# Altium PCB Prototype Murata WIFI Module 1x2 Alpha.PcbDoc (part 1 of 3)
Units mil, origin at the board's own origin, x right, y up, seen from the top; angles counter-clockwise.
Board outline 708.66 x 1594.49 mil, 6 copper layers (Component Side, Ground Plane (GND), Inner Layer 1, Inner Layer 2, Power Plane (VCC), Solder Side), stack 20.279 mil thick; 197 components, 116 nets, 943 pads, 479 vias.
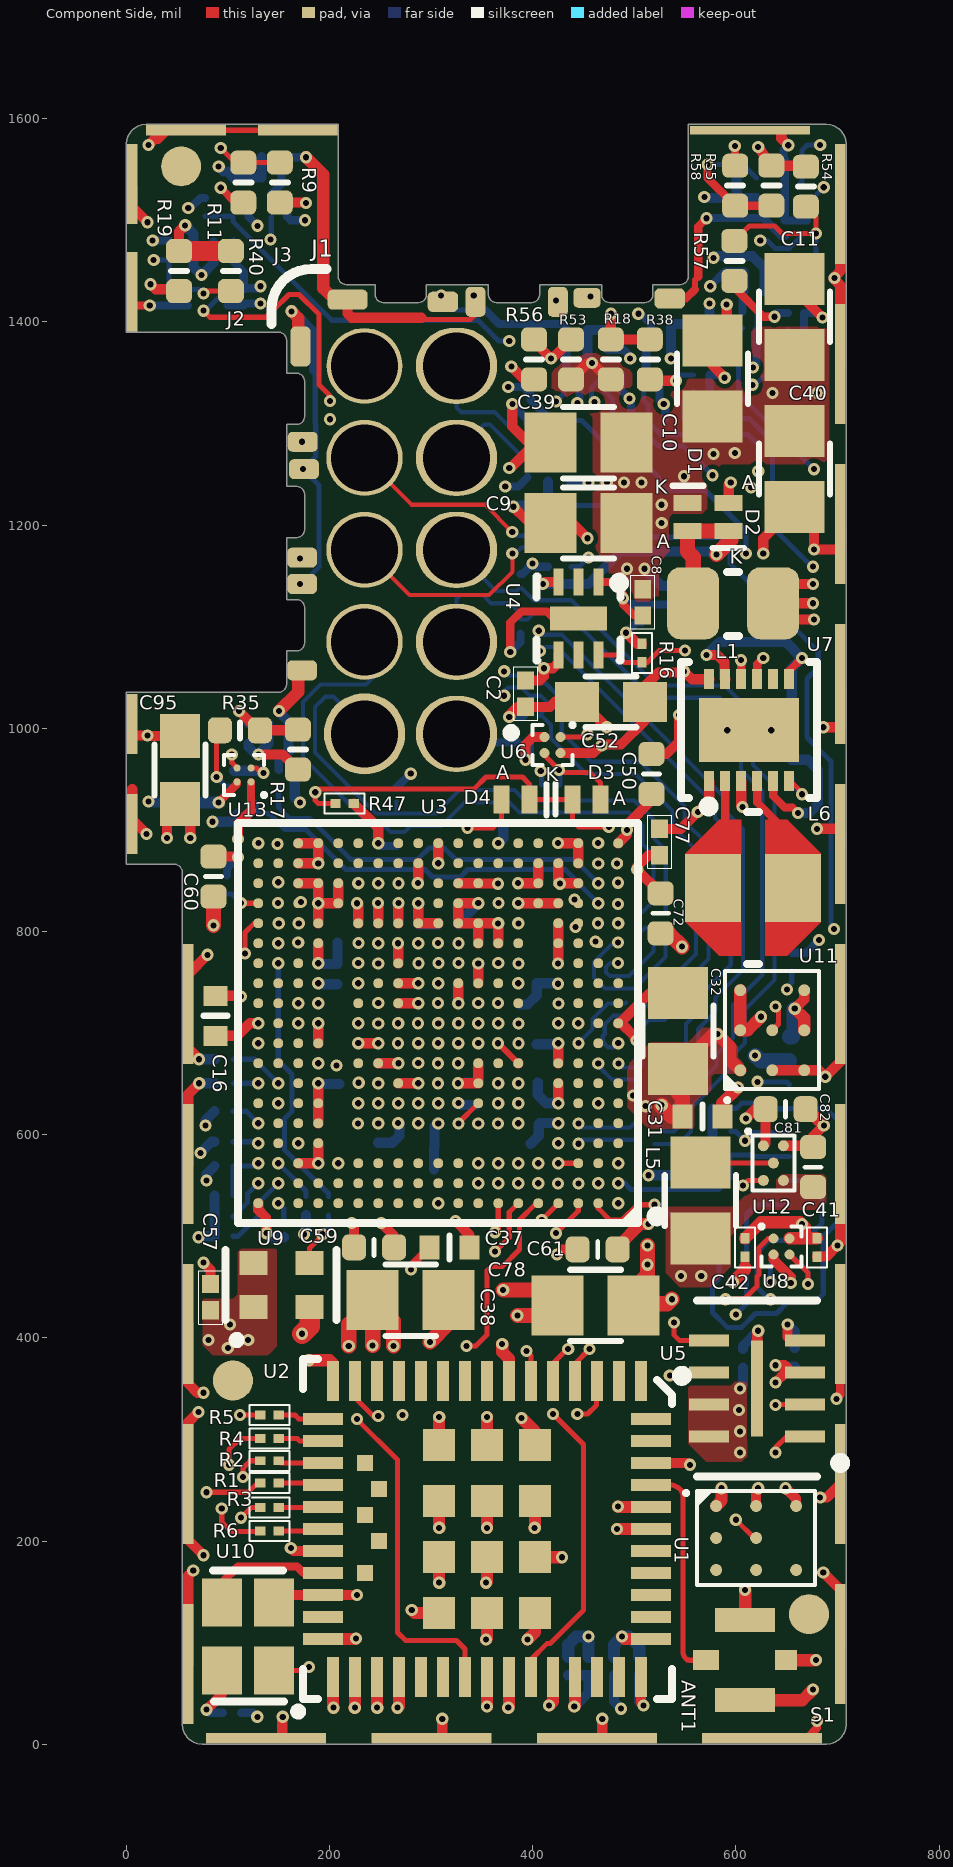
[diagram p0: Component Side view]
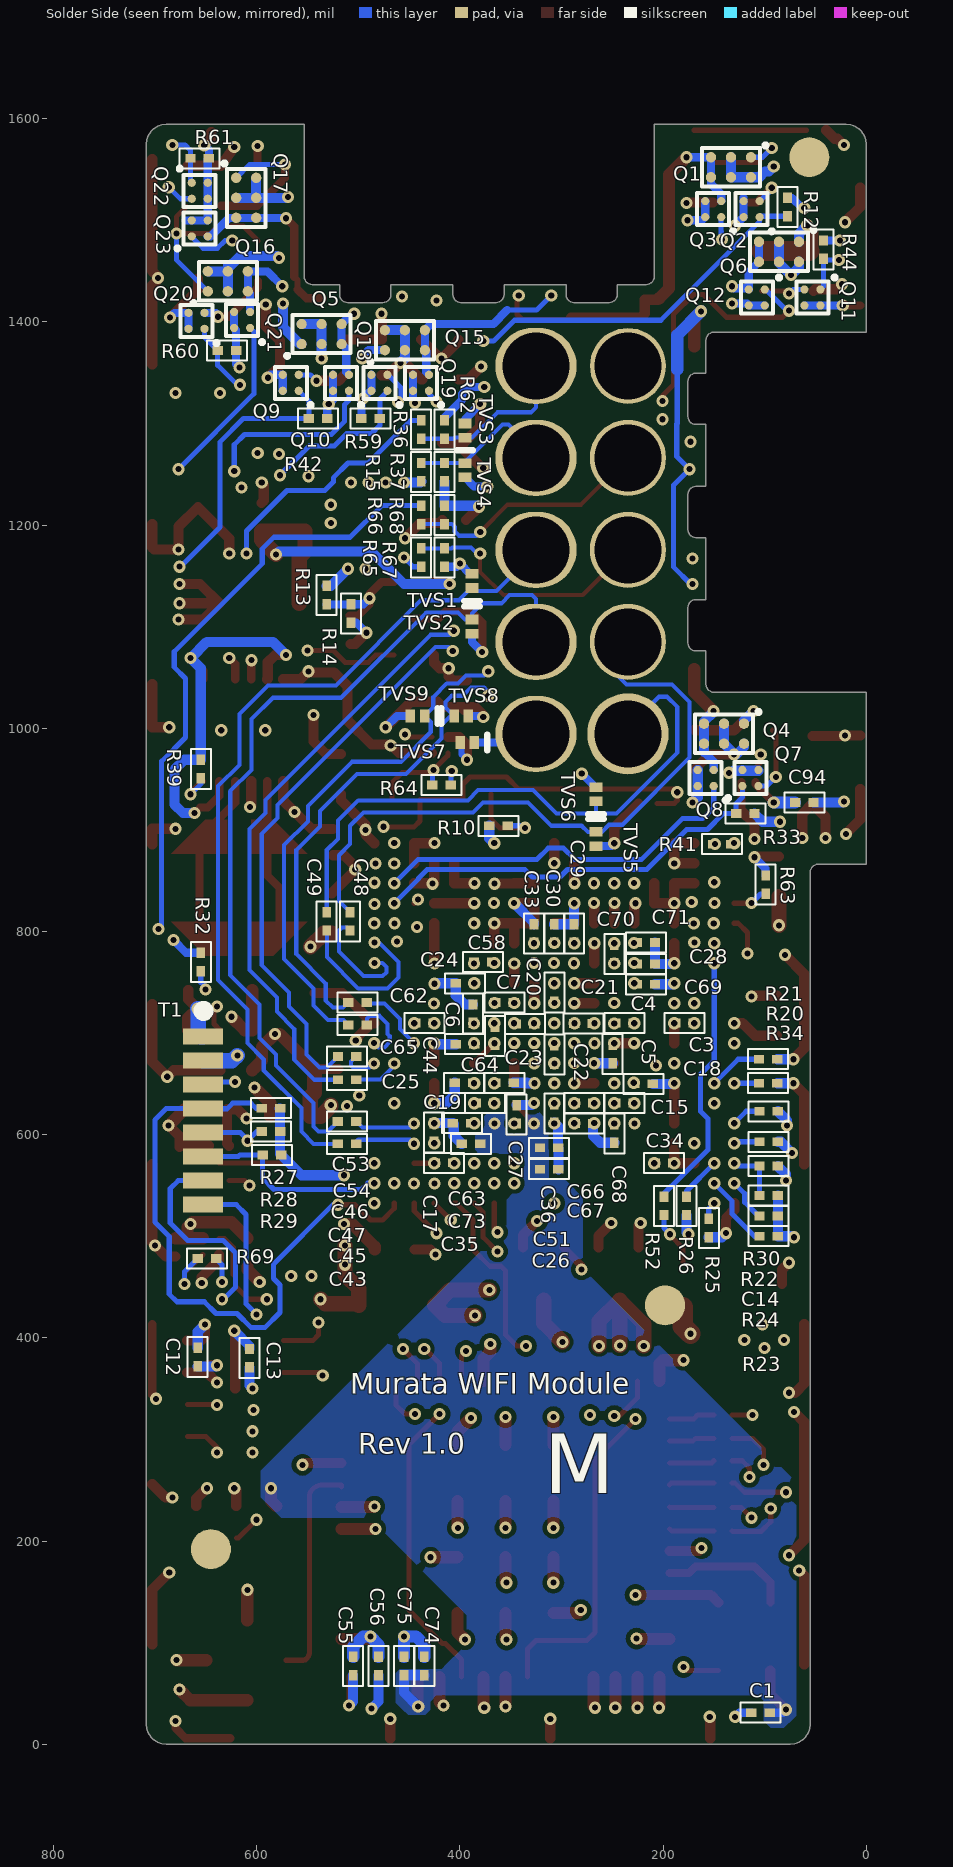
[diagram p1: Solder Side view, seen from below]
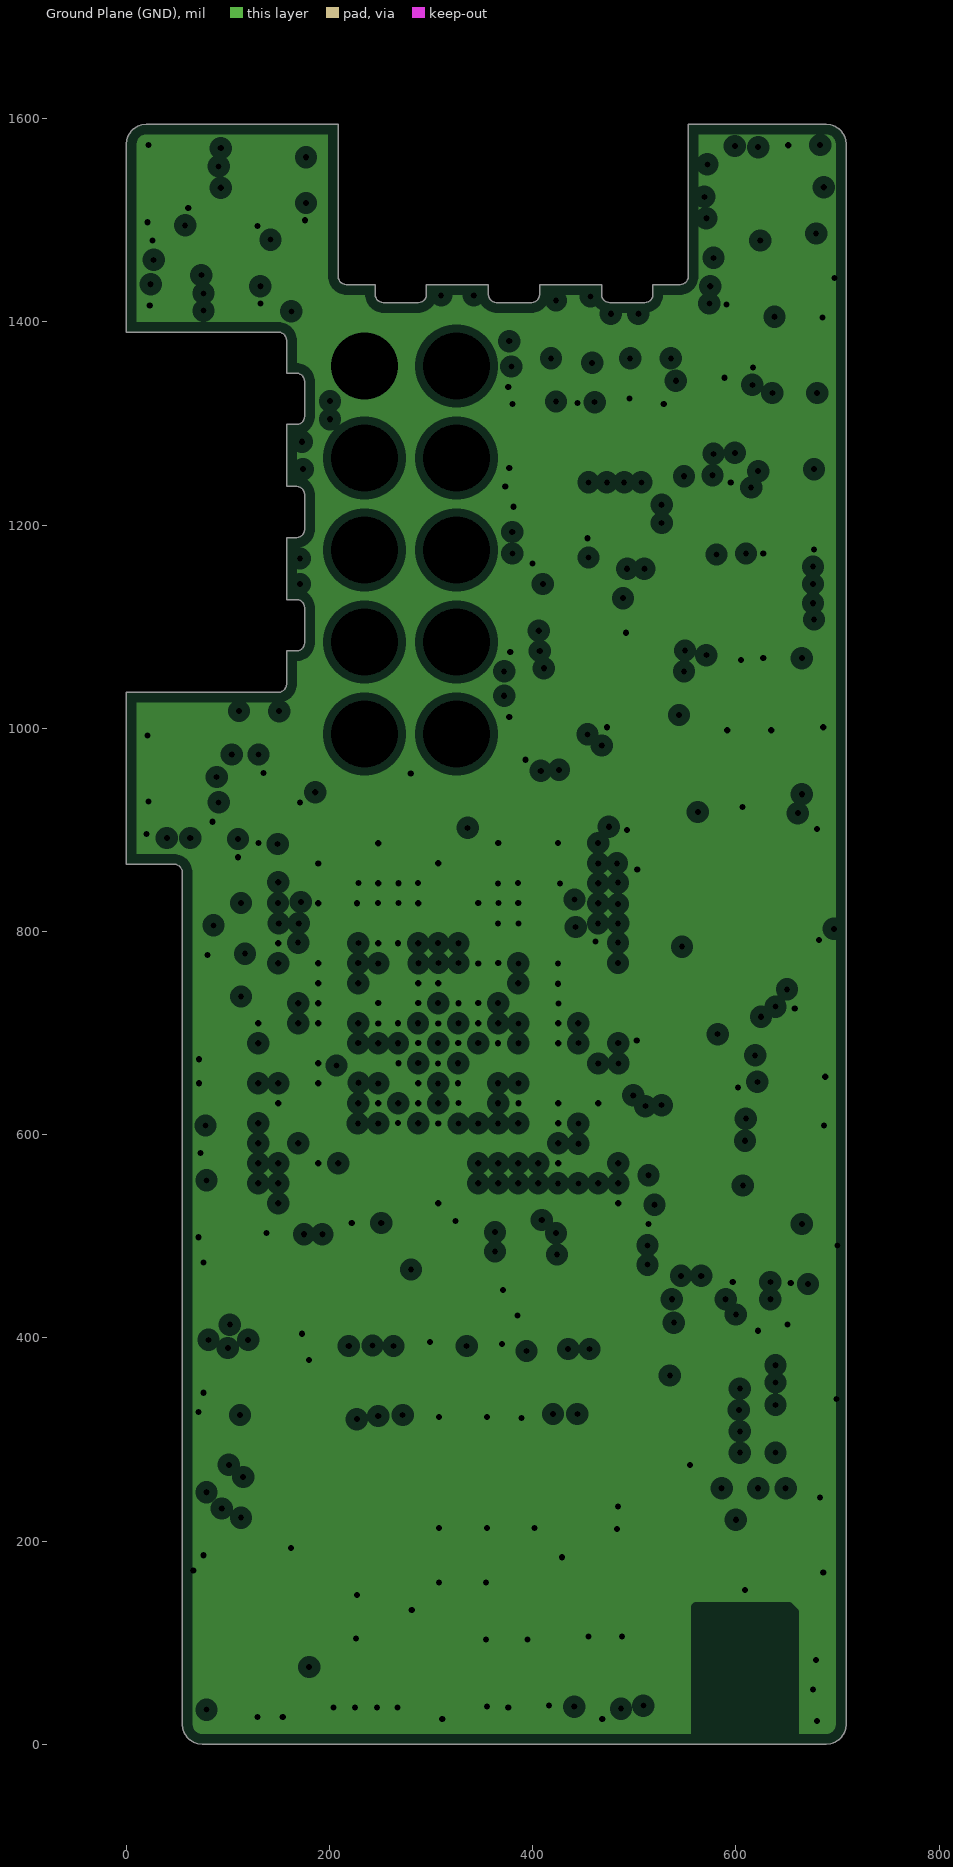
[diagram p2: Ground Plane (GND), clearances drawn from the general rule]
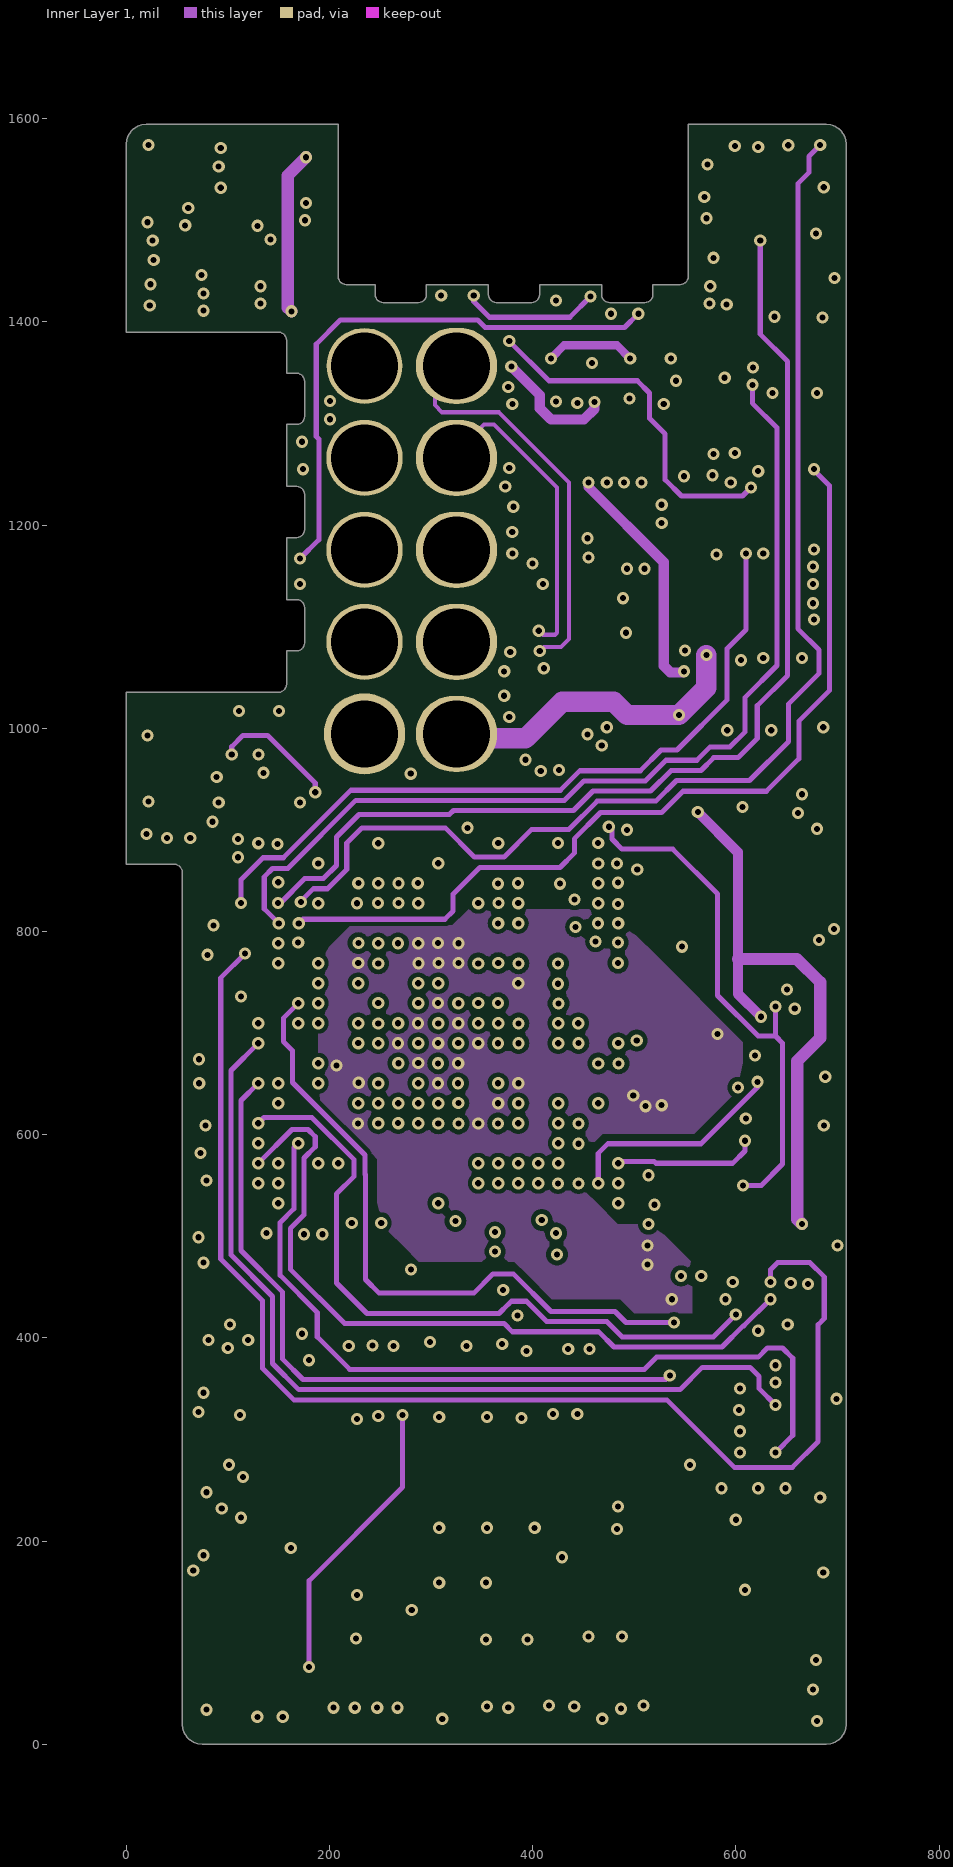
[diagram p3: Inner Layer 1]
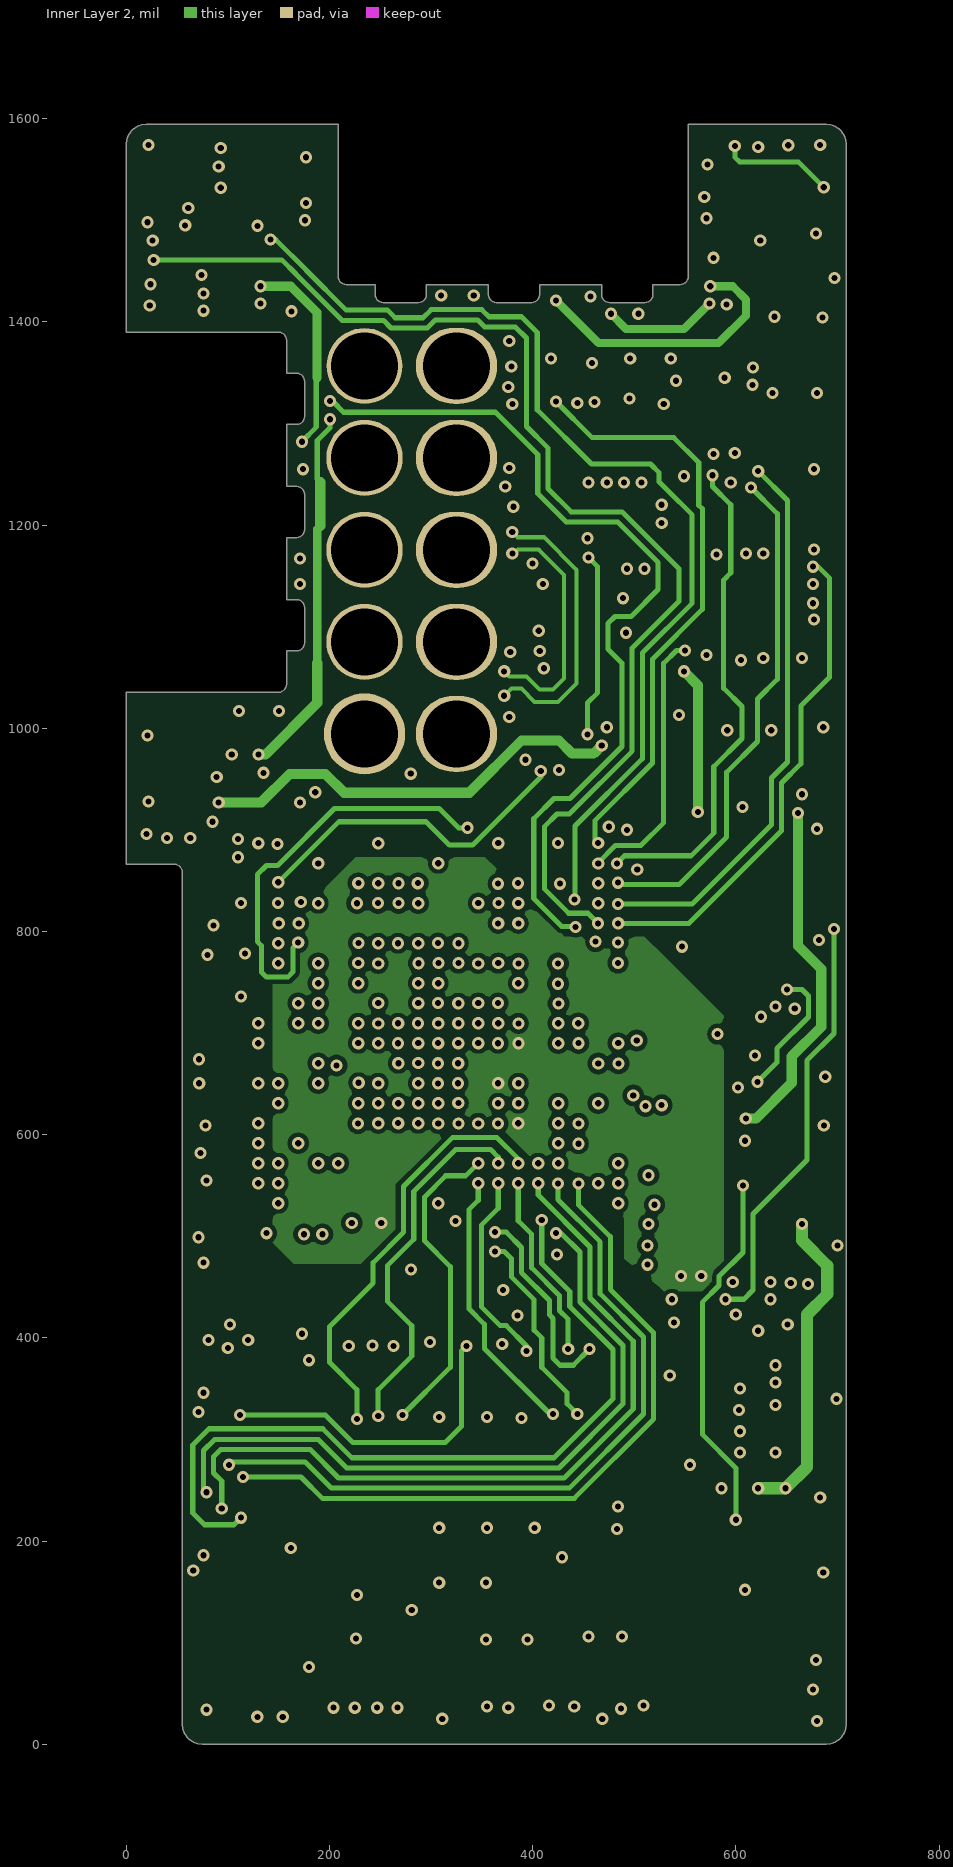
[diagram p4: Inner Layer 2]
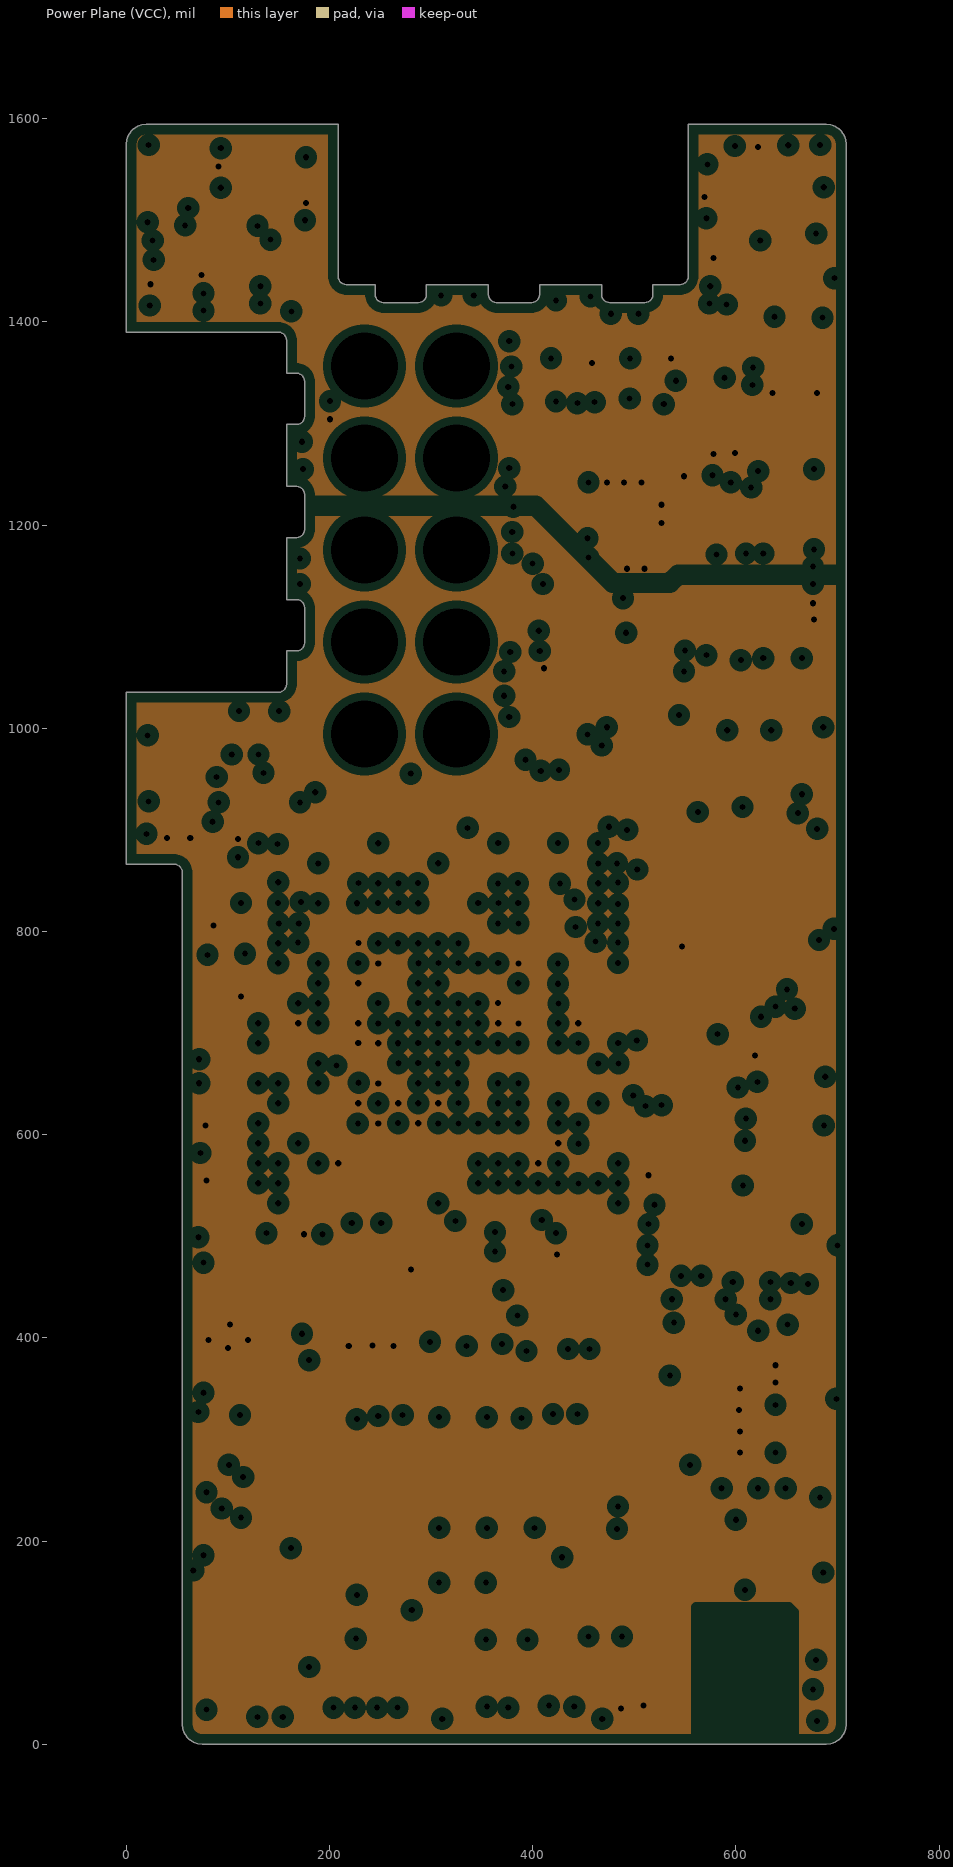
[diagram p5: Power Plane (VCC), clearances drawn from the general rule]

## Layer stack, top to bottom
Component Side: signal copper 1.4
Dielectric: core 1.9685, FR-4, Dk 4.8
Ground Plane (GND): plane copper 1.4169, net GND
Dielectric: prepreg 1.9685, Dk 4.2
Inner Layer 1: signal copper 1.4169
Dielectric: core 3.937, Dk 4.2
Inner Layer 2: signal copper 1.4169
Dielectric: prepreg 1.9685, Dk 4.2
Power Plane (VCC): plane copper 1.4169, net (Multiple Nets)
Dielectric: core 1.9685, Dk 4.2
Solder Side: signal copper 1.4

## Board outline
157.87,1076.18 157.87,1043.31 157.68,1041.55 157.09,1039.89 156.16,1038.4 154.91,1037.15 153.42,1036.21 151.75,1035.63 150,1035.43 0,1035.43 0,866.14 47.24,866.14 49,865.94 50.66,865.36 52.15,864.42 53.4,863.18 54.34,861.68 54.92,860.02 55.12,858.27 55.12,19.68 55.61,15.3 57.07,11.14 59.41,7.41 62.53,4.29 66.26,1.95 70.42,0.49 74.8,0 688.98,0 693.36,0.49 697.52,1.95 701.25,4.29 704.37,7.41 706.71,11.14 708.17,15.3 708.66,19.68 708.66,1574.8 708.17,1579.18 706.71,1583.34 704.37,1587.08 701.25,1590.19 697.52,1592.54 693.36,1593.99 688.98,1594.49 553.15,1594.49 553.15,1444.49 552.95,1442.74 552.37,1441.07 551.43,1439.58 550.18,1438.33 548.69,1437.39 547.03,1436.81 545.28,1436.61 518.31,1436.61 518.31,1426.77 518.11,1425.02 517.53,1423.36 516.59,1421.86 515.34,1420.62 513.85,1419.68 512.19,1419.09 510.43,1418.9 475.79,1418.9 474.04,1419.09 472.37,1419.68 470.88,1420.62 469.63,1421.86 468.69,1423.36 468.11,1425.02 467.91,1426.77 467.91,1436.61 406.89,1436.61 406.89,1426.77 406.69,1425.02 406.11,1423.36 405.17,1421.86 403.93,1420.62 402.43,1419.68 400.77,1419.09 399.02,1418.9 364.37,1418.9 362.62,1419.09 360.95,1419.68 359.46,1420.62 358.21,1421.86 357.28,1423.36 356.69,1425.02 356.5,1426.77 356.5,1436.61 295.47,1436.61 295.47,1426.77 295.27,1425.02 294.69,1423.36 293.75,1421.86 292.51,1420.62 291.01,1419.68 289.35,1419.09 287.6,1418.9 252.95,1418.9 251.2,1419.09 249.54,1419.68 248.04,1420.62 246.8,1421.86 245.86,1423.36 245.28,1425.02 245.08,1426.77 245.08,1436.61 216.54,1436.61 214.78,1436.81 213.12,1437.39 211.63,1438.33 210.38,1439.58 209.44,1441.07 208.86,1442.74 208.66,1444.49 208.66,1594.49 19.68,1594.49 15.3,1593.99 11.14,1592.54 7.41,1590.19 4.29,1587.08 1.95,1583.34 0.49,1579.18 0,1574.8 0,1389.76 150,1389.76 151.75,1389.57 153.42,1388.98 154.91,1388.05 156.16,1386.8 157.09,1385.31 157.68,1383.64 157.87,1381.89 157.87,1349.41 167.72,1349.41 169.47,1349.21 171.13,1348.63 172.63,1347.69 173.87,1346.44 174.81,1344.95 175.39,1343.29 175.59,1341.54 175.59,1306.89 175.39,1305.14 174.81,1303.47 173.87,1301.98 172.63,1300.73 171.13,1299.8 169.47,1299.21 167.72,1299.02 157.87,1299.02 157.87,1237.99 167.72,1237.99 169.47,1237.79 171.13,1237.21 172.63,1236.27 173.87,1235.03 174.81,1233.53 175.39,1231.87 175.59,1230.12 175.59,1195.47 175.39,1193.72 174.81,1192.06 173.87,1190.56 172.63,1189.32 171.13,1188.38 169.47,1187.8 167.72,1187.6 157.87,1187.6 157.87,1126.57 167.72,1126.57 169.47,1126.38 171.13,1125.79 172.63,1124.86 173.87,1123.61 174.81,1122.12 175.39,1120.45 175.59,1118.7 175.59,1084.05 175.39,1082.3 174.81,1080.64 173.87,1079.15 172.63,1077.9 171.13,1076.96 169.47,1076.38 167.72,1076.18

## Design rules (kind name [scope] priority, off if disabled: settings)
Clearance diff_1 [InNetClass('diff')] p1: gap=5
Clearance [All] p2: gap=4.5
DiffPairsRouting [All] p1: maxlimit=8 minlimit=8 mostfreqgap=8 maxuncoupledlength=500
FabricationTestPointUsage [All] p1 off: valid=0 allowmultiple=FALSE
FabricationTestpoint [(IsPad And (OnTopLayer Or OnBottomLayer))] p1 off: side=3 testpointundercomponent=TRUE minsize=40 maxsize=100 preferedsize=60 minholesize=0 maxholesize=40 preferedholesize=32 testpointgrid=1 allowsidetop=TRUE allowsidebottom=TRUE usegrid=TRUE gridtolerance=0.01
MatchedLengths DiffPair_MatchedLengths [InDifferentialPair ('SERDES_TX_CHIP')] p1: tolerance=1000 checknetsindiffpair=TRUE checkdiffpairvsdiffpair=TRUE checkothers=TRUE
MatchedLengths DiffPair_MatchedLengths_1 [InDifferentialPair ('SERDES_TX')] p2: tolerance=1000 checknetsindiffpair=TRUE checkdiffpairvsdiffpair=TRUE checkothers=TRUE
MatchedLengths DiffPair_MatchedLengths_2 [InDifferentialPair ('SERDES_RX')] p3: tolerance=1000 checknetsindiffpair=TRUE checkdiffpairvsdiffpair=TRUE checkothers=TRUE
MatchedLengths DiffPair_MatchedLengths_3 [InDifferentialPair ('RCLK_100MHZ')] p4: tolerance=1000 checknetsindiffpair=TRUE checkdiffpairvsdiffpair=TRUE checkothers=TRUE
MatchedLengths DiffPair_MatchedLengths_4 [InDifferentialPair ('OSC_100MHZ')] p5: tolerance=1000 checknetsindiffpair=TRUE checkdiffpairvsdiffpair=TRUE checkothers=TRUE
MinimumSolderMaskSliver [All] p1: minsoldermaskwidth=3
PlaneClearance [All] p1: clearance=8
PlaneConnect [All] p1: planeconnectstyle=Direct reliefexpansion=8 reliefentries=4 reliefconductorwidth=8 reliefairgap=8
PolygonConnect [All] p1: connectstyle=Direct reliefconductorwidth=10 reliefentries=4 polygonreliefangle="90 Angle"
RoutingVias [All] p1: holewidth=6 width=12 viastyle="Through Hole" minholewidth=6 minwidth=12 maxholewidth=6 maxwidth=12
SilkToSilkClearance [All] p1: silktosilkclearance=3
SilkscreenOverComponentPads SilkToSolderMaskClearance [IsPad] p1: minsilkscreentomaskgap=3
SolderMaskExpansion [All] p1: expansion=4
Width diff [InNetClass('diff')] p1: maxlimit=4 minlimit=4 preferedwidth=4
Width [All] p2: maxlimit=30 minlimit=4 preferedwidth=5
20 further rules are at their usual default settings.

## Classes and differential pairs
differential pair TX: +TX_P -TX_N
differential pair TX_CLK: +TX_CLK_P -TX_CLK_N
differential pair RX: +RX_P -RX_N
differential pair RX_CLK: +RX_CLK_P -RX_CLK_N
differential pair C_TX: +C_TX_P -C_TX_N
differential pair C_TX_CLK: +C_TX_CLK_P -C_TX_CLK_N
differential pair C_RX: +C_RX_P -C_RX_N
differential pair C_RX_CLK: +C_RX_CLK_P -C_RX_CLK_N

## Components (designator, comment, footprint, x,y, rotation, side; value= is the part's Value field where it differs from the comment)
ANT1 "Ultra Miniature Coaxial" W.FL2-R-SMT-1 609.25,82.68 r270 top locked
C1 "0.1uF" C_01005#1 104,31 r180 bottom
C2 "0.1uF" CAPC0201 393,1034 r90 top
C3 "0.1uF" C_01005#2 179,710 r180 bottom
C4 "0.1uF" C_01005#2 238,710 r180 bottom
C5 "0.1uF" C_01005#2 249.51,679.24 r90 bottom
C6 "0.1uF" C_01005#2 387,719 r270 bottom
C7 "0.1uF" C_01005#2 356,730 r0 bottom
C8 "C_0201_22pF" CAPC0201 508.42,1124 r90 top
C9 "22µF" C_ERA-0805 454.79,1202 r0 top
C10 "22µF" C_ERA-0805 577,1344 r270 top
C11 "22µF" C_ERA-0805 657.7,1405 r270 top
C12 "0.1uF" C_01005#2 658,381 r90 bottom
C13 "0.1uF" C_01005#2 607,380 r90 bottom
C14 "0.1uF" C_01005#2 96,540 r180 bottom
C15 "0.1uF" C_01005#2 238,631 r0 bottom
C16 "1.0uF" C_ERA-0402 88,717 r90 top
C17 "0.1uF" C_01005#2 425.51,602.24 r90 bottom
C18 "0.1uF" C_01005#2 219,650 r0 bottom
C19 "0.1uF" C_01005#2 375,631 r180 bottom
C20 "0.1uF" C_01005#2 307,740 r270 bottom
C21 "0.1uF" C_01005#2 278.51,709.24 r0 bottom
C22 "0.1uF" C_01005#2 307,679 r90 bottom
C23 "0.1uF" C_01005#2 336,709 r180 bottom
C24 "0.1uF" C_01005#2 395,749 r180 bottom
C25 "0.1uF" C_01005#2 396,651 r180 bottom
C26 "0.1uF" C_01005#2 312,566 r0 bottom
C27 "0.1uF" C_01005#2 344,620 r270 bottom
C28 "0.1uF" C_01005#2 217,768 r0 bottom
C29 "0.1uF" C_01005#2 287.5,798 r270 bottom
C30 "0.1uF" C_01005#2 307,798 r270 bottom
C31 "1.0uF" C_ERA-0402 567,618 r180 top
C32 "22uF" C_ERA-0805 543,702 r270 top
C33 "0.1uF" C_01005#2 327,798 r270 bottom
C34 "0.1uF" C_01005#2 199,572 r0 bottom
C35 "0.1uF" C_01005#2 415.51,572.24 r180 bottom
C36 "0.1uF" C_01005#2 307,621 r90 bottom
C37 "1.0uF" C_ERA-0402 318,489 r180 top
C38 "22uF" C_ERA-0805 280,437 r180 top
C39 "22µF" C_ERA-0805 454.87,1281 r0 top
C40 "22µF" C_ERA-0805 657.8,1255 r90 top
C41 "0.1UF" C_01005#1 680,489 r90 top
C42 "0.1uF" C_01005#1 609,489 r90 top
C43 "0.1uF" C_01005#2 511.04,591 r180 bottom
C44 "0.1uF" C_01005#2 365.51,697.24 r90 bottom
C45 "0.1uF" C_01005#2 510.95,613 r180 bottom
C46 "0.1uF" C_01005#2 510.85,677 r180 bottom
C47 "0.1uF" C_01005#2 510.85,654 r180 bottom
C48 "0.1uF" C_01005#2 508.06,810 r270 bottom
C49 "0.1uF" C_01005#2 531,810 r270 bottom
C50 "10uF" C_0402 517,955 r90 top
C51 "0.1uF" C_01005#2 312,587 r0 bottom
C52 "22uF" C_ERA-0603 477,1026 r0 top
C53 "0.1uF" C_01005#2 500.73,730 r180 bottom
C54 "0.1uF" C_01005#2 500.59,708 r180 bottom
C55 "0.1uF" C_01005#1 505,77 r270 bottom
C56 "0.1uF" C_01005#1 480,77 r270 bottom
C57 "0.47µF" CAPC0201 83,440 r270 top
C58 "0.1uF" C_01005#2 377,770 r0 bottom
C59 "10uF" C_0402 244,489 r0 top
C60 "10uF" C_0402 85.91,854 r270 top
C61 "10uF" C_0402 464,487 r180 top
C62 "0.1uF" C_01005#2 435,710 r0 bottom
C63 "0.1uF" C_01005#2 398,611.3 r180 bottom
C64 "0.1uF" C_01005#2 356,651 r0 bottom
C65 "0.1uF" C_01005#2 395,689 r180 bottom
C66 "0.1uF" C_01005#2 278,631 r180 bottom
C67 "0.1uF" C_01005#2 278,611 r0 bottom
C68 "0.1uF" C_01005#2 248,601 r90 bottom
C69 "0.1uF" C_01005#2 217,748 r0 bottom
C70 "0.1uF" C_01005#2 248,778 r270 bottom
C71 "0.1uF" C_01005#2 217,789 r0 bottom
C72 "10uF" C_0402 526,817.81 r270 top
C73 "0.1uF" C_01005#2 389,591 r180 bottom
C74 "0.1uF" C_01005#1 435,77 r270 bottom
C75 "0.1uF" C_01005#1 455,77 r270 bottom
C77 "0.47µF" CAPC0201 525,888 r90 top
C78 "22uF" C_ERA-0805 462,432 r0 top
C81 "4.7uF" C_0402 649,625 r180 top
C82 "10uF" C_0402 676,568 r270 top
C94 "0.1uF" C_01005#2 61,927 r0 bottom
C95 "22uF" C_ERA-0603 53,959 r270 top
D1 "SBR0240LP-7" 2-XFDFN 552.45,1208 r270 top
D2 "SBR0240LP-7" 2-XFDFN 593,1208 r90 top
D3 "SBR0240LP-7" 2-XFDFN 453,930 r0 top
D4 "SBR0240LP-7" 2-XFDFN 383,930 r180 top
J1 "EPM" EPM_3X_CON_BO 239,1434 r90 top
J2 "EPM" EPM_3X_CON_FRANK 159.38,1354.68 r180 top locked
J3 "SPRING PIN" "10PIN SMD CONNECTOR" 325.08,994.4 r90 top locked
L1 "CBC2016T220K" L_0806 597.39,1123 r0 top
L5 "2.2uH" C_ERA-0805 565,535 r270 top
L6 "2.2uH Wirewound" L_SMD_2.2UH 617,843 r180 top
Q1 "SI8497DB-T2-E1" BGA6C50P3X2_145X96X59 133.13,1552.13 r0 bottom
Q2 "SI8808DB-T2-E1" BGA4C40P2X2_80X80X40 112.75,1511 r90 bottom
Q3 "SI8808DB-T2-E1" BGA4C40P2X2_80X80X40 150.59,1511 r90 bottom
Q4 "SI8497DB-T2-E1" BGA6C50P3X2_145X96X59 140,994.68 r0 bottom
Q5 "SI8497DB-T2-E1" BGA6C50P3X2_145X96X59 536.08,1388 r180 bottom
Q6 "SI8497DB-T2-E1" BGA6C50P3X2_145X96X59 85.91,1469 r0 bottom
Q7 "SI8808DB-T2-E1" BGA4C40P2X2_80X80X40 114,951 r180 bottom
Q8 "SI8808DB-T2-E1" BGA4C40P2X2_80X80X40 158,951 r90 bottom
Q9 "SI8808DB-T2-E1" BGA4C40P2X2_80X80X40 566.4,1340 r90 bottom
Q10 "SI8808DB-T2-E1" BGA4C40P2X2_80X80X40 517,1340 r90 bottom
Q11 "SI8808DB-T2-E1" BGA4C40P2X2_80X80X40 53.01,1424 r0 bottom
Q12 "SI8808DB-T2-E1" BGA4C40P2X2_80X80X40 107.76,1424 r0 bottom
Q15 "SI8497DB-T2-E1" BGA6C50P3X2_145X96X59 454.06,1382 r180 bottom
Q16 "SI8497DB-T2-E1" BGA6C50P3X2_145X96X59 628.32,1439.84 r180 bottom
Q17 "SI8497DB-T2-E1" BGA6C50P3X2_145X96X59 610.35,1522 r270 bottom
Q18 "SI8808DB-T2-E1" BGA4C40P2X2_80X80X40 479.16,1340 r90 bottom
Q19 "SI8808DB-T2-E1" BGA4C40P2X2_80X80X40 438.25,1340 r90 bottom
Q20 "SI8808DB-T2-E1" BGA4C40P2X2_80X80X40 659.19,1401 r90 bottom
Q21 "SI8808DB-T2-E1" BGA4C40P2X2_80X80X40 614.32,1401.84 r90 bottom
Q22 "SI8808DB-T2-E1" BGA4C40P2X2_80X80X40 656,1529 r270 bottom
Q23 "SI8808DB-T2-E1" BGA4C40P2X2_80X80X40 656,1492 r180 bottom
R1 "33" R_01005#1 141,257 r0 top
R2 "33" R_01005#1 141,279 r0 top
R3 "33" R_01005#1 141,233 r0 top
R4 "33" R_01005#1 141,301 r0 top
R5 "33" R_01005#1 141,324 r0 top
R6 "33" R_01005#1 141,210 r0 top
R9 "100" R_0402 151.13,1537.13 r90 top
R10 "10K" R_01005#2 362,904 r180 bottom
R11 "270" R_0402 115.17,1537 r270 top
R12 "1k" R_01005#2 77.38,1513 r90 bottom
R13 "10K" R_01005#2 531,1131 r270 bottom
R14 "4.7k" R_01005#2 507,1113 r270 bottom
R15 "10K" R_01005#2 438,1252 r270 bottom
R16 "1k" R_01005#1 507.63,1073.94 r90 top
R17 "100" R_0402 169,979 r90 top
R18 "100" R_0402 476.9,1363 r90 top
R19 "100" R_0402 52.01,1450 r90 top
R20 "1k" R_01005#2 96.46,650.59 r0 bottom
R21 "1k" R_01005#2 96.46,674.21 r180 bottom
R22 "10K" R_01005#2 96,569 r0 bottom
R23 "10K" R_01005#2 96,500 r180 bottom
R24 "10K" R_01005#2 96,520 r180 bottom
R25 "10K" R_01005#2 155,508 r270 bottom
R26 "10K" R_01005#2 177,530 r270 bottom
R27 "4.7k" R_01005#2 586,626 r0 bottom
R28 "4.7k" R_01005#2 586,603 r0 bottom
R29 "4.7k" R_01005#2 585,580.06 r0 bottom
R30 "10K" R_01005#2 96,593 r180 bottom
R32 "4.7k" R_01005#2 655,770 r90 bottom
R33 "10K" R_01005#2 141.73,885.83 r180 bottom
R34 "10K" R_01005#2 96,623 r180 bottom
R35 "270" R_0402 112,998 r180 top
R36 "10K" R_01005#2 438,1294 r90 bottom
R37 "1M Ohms" R_01005#2 415,1252 r270 bottom
R38 "270" R_0402 515.31,1363 r270 top
R39 "10K" R_01005#2 655,960 r270 bottom
R40 "270" R_0402 103,1450 r270 top
R41 "1k" R_01005#2 119,916 r180 bottom
R42 "1k" R_01005#2 539.6,1305 r180 bottom
R44 "1k" R_01005#2 42,1471 r90 bottom
R47 "100K" R_01005#1 215,926 r0 top
R52 "33" R_01005#2 199,530 r90 bottom
R53 "100" R_0402 437.95,1363 r90 top
R54 "100" R_0402 669,1533 r270 top
R55 "100" R_0402 635,1534 r270 top
R56 "270" R_0402 401.41,1363 r270 top
R57 "270" R_0402 598.6,1460 r270 top
R58 "270" R_0402 599.39,1534 r90 top
R59 "1k" R_01005#2 487.84,1305 r0 bottom
R60 "1k" R_01005#2 629.32,1371.84 r180 bottom
R61 "1k" R_01005#2 656,1561 r180 bottom
R62 "1M Ohms" R_01005#2 415,1294 r90 bottom
R63 "1k" R_01005#2 99,846 r270 bottom
R64 "10K" R_01005#2 417.94,944 r180 bottom
R65 "10K" R_01005#2 438,1168 r270 bottom
R66 "10K" R_01005#2 438,1210 r90 bottom
R67 "1M Ohms" R_01005#2 415,1168 r270 bottom
R68 "1M Ohms" R_01005#2 415,1210 r90 bottom
R69 "10K" R_01005#2 649,478 r180 bottom
S1 "RFSHIELD" RFSHIELD_1X2_MODULE 0,0 r0 top locked
T1 "8 PIN TEST_INTERFACE" "8-PIN TEST INTERFACE" 652.76,613.78 r180 bottom locked
TVS1 "TVS_HS_ESD" TSSLP-2-1 388,1145 r90 bottom
TVS2 "TVS_HS_ESD" TSSLP-2-1 388,1100 r270 bottom
TVS3 "TVS_HS_ESD" TSSLP-2-1 395,1293 r90 bottom
TVS4 "TVS_HS_ESD" TSSLP-2-1 395,1254 r270 bottom
TVS5 "TVS_HS_ESD" TSSLP-2-1 266,891 r270 bottom
TVS6 "TVS_HS_ESD" TSSLP-2-1 266,935 r90 bottom
TVS7 "TVS_HS_ESD" TSSLP-2-1 392.69,986 r0 bottom
TVS8 "TVS_HS_ESD" TSSLP-2-1 398.62,1012 r180 bottom
TVS9 "TVS_HS_ESD" TSSLP-2-1 441.68,1012 r0 bottom
U1 "U_TPS82671SIPT" "MICRP SIP"#1 620,203 r0 top
U2 "MURATA WIFI Module" SP-9XUH-D 355,212 r180 top
U3 "LFE3-17EA" BGA328C50P19X19_1000X1000X150 307.09,709.65 r180 top locked
U4 "U_LT3460EDC-1" DFN6 445,1108 r180 top
U5 "M25P16-VMC6TG" UFDFN8 621,350 r180 top
U6 "Buffer" DSBGA4_.4MM 419.59,983.5 r270 top
U7 "3.3V STEP UP/DOWN" QFN40P300X300X80_HS-13L 613.19,998.03 r0 top
U8 "Buffer" DSBGA4_.4MM 645,490 r0 top
U9 "19.2MHz Oscillator" LCCS165P160X200X70-4N 153,452 r0 top
U10 "32.768KHz Oscillator" KX2513G0032.768000 120,106 r90 top
U11 "TPS82675SIPT" "MICRP SIP"#2 635.83,702.76 r90 top
U12 "2.5V Buck Converter" BGA4C50P2X2_105X138X60 637,572 r270 top
U13 "Power Switch" DSBGA4 116,954 r90 top
? "Comment" FID_FAIRCHILD -140,1399 r0 top

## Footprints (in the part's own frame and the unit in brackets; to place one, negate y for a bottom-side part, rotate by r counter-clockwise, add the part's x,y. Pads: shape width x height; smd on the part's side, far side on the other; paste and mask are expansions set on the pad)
2-XFDFN [mm] "2-XFDFN"
  rect 0.4x0.7 smd mask+0: 1(0.35,0) 2(-0.35,0)
  silkscreen extent -0.78,-0.38 -0.78,0.4
"8-PIN TEST INTERFACE" [mm] "SOIC, 4-Leads, Body 3.7x6.0mm (max), Pitch 1.27mm, IPC High Density"
  rect 1x0.4 smd paste+0 mask+0: 1(0,2.1) 2(0,1.5) 3(0,0.9) 4(0,0.3) 5(0,-0.3) 6(0,-0.9) 7(0,-1.5) 8(0,-2.1)
  silkscreen extent -0.11,2.62 0.14,2.87
"10PIN SMD CONNECTOR" [mil] "10PIN TONKA MODULE CONNECTOR"
  oval 75x80 hole 66 paste+0 mask+0: 1(0,0) 3(90.55,0) 5(181.1,0) 7(271.65,0) 9(362.2,0)
  round 80 hole 66 paste+0 mask+0: 2(0,90.55)
  round 75 hole 66 paste+0 mask+0: 4(90.55,90.55) 6(181.1,90.55) 8(271.65,90.55)
  round 74.8 hole 66 paste+0 mask+0: 10(362.2,90.55)
  silkscreen extent -2,-57 458,182, body extent -36,-36 398,127, height 16
BGA4C40P2X2_80X80X40 [mm] "BGA, 4-Leads, Body 0.80x0.80mmx0.40mm, Pitch 0.40mm"
  round 0.205 smd paste+0 mask+0: 1(-0.2,-0.2) 2(-0.2,0.2) 3(0.2,0.2) 4(0.2,-0.2)
  silkscreen extent -0.6,-0.55 0.4,0.4, body extent -0.4,-0.4 0.4,0.4, height 0.4
BGA4C50P2X2_105X138X60 [mm] "BGA, 4-Leads, Body 1.05x1.38mmx0.60mm, Pitch 0.50mm"
  round 0.275 smd mask+0: A1(-0.433,-0.25) A3(-0.433,0.25) B2(0,0) C1(0.433,-0.25) C3(0.433,0.25)
  silkscreen extent -0.84,-0.68 0.69,0.53, body extent -0.69,-0.52 0.69,0.53, height 0.6
BGA6C50P3X2_145X96X59 [mm] "BGA, 6-Leads, Body 1.45x0.96mmx0.59mm, Pitch 0.50mm"
  round 0.26 smd paste+0 mask+0: 1(-0.5,-0.25) 2(-0.5,0.25) 3(0,0.25) 4(0.5,0.25) 5(0.5,-0.25) 6(0,-0.25)
  silkscreen extent -0.91,-0.59 0.72,0.48, body extent -0.72,-0.48 0.72,0.48, height 0.59
BGA328C50P19X19_1000X1000X150 [mm] "BGA, 328-Leads, Body 10.00x10.00mmx1.50mm, Pitch 0.50mm"
  round 0.25 smd mask+0: A1(-4.5,4.5) A2(-4,4.5) A3(-3.5,4.5) A4(-3,4.5) A5(-2.5,4.5) A6(-2,4.5) A7(-1.5,4.5) A8(-1,4.5) A9(-0.5,4.5) A10(0,4.5) A11(0.5,4.5) A12(1,4.5) A13(1.5,4.5) A14(2,4.5) A15(2.5,4.5) A16(3,4.5) A17(3.5,4.5) A18(4,4.5) A19(4.5,4.5) B1(-4.5,4) B2(-4,4) B3(-3.5,4) B4(-3,4) B5(-2.5,4) B6(-2,4) B7(-1.5,4) B8(-1,4) B9(-0.5,4) B10(0,4) B11(0.5,4) B12(1,4) B13(1.5,4) B14(2,4) B15(2.5,4) B16(3,4) B17(3.5,4) B18(4,4) B19(4.5,4) C1(-4.5,3.5) C2(-4,3.5) C3(-3.5,3.5) C4(-3,3.5) C5(-2.5,3.5) C6(-2,3.5) C7(-1.5,3.5) C8(-1,3.5) C9(-0.5,3.5) C10(0,3.5) C11(0.5,3.5) C12(1,3.5) C13(1.5,3.5) C14(2,3.5) C15(2.5,3.5) C16(3,3.5) C17(3.5,3.5) C18(4,3.5) C19(4.5,3.5) D1(-4.5,3) D2(-4,3) D3(-3.5,3) D4(-3,3) D16(3,3) D17(3.5,3) D18(4,3) D19(4.5,3) E1(-4.5,2.5) E2(-4,2.5) E3(-3.5,2.5) E4(-3,2.5) E6(-2,2.5) E7(-1.5,2.5) E8(-1,2.5) E9(-0.5,2.5) E10(0,2.5) E11(0.5,2.5) E12(1,2.5) E13(1.5,2.5) E14(2,2.5) E16(3,2.5) E17(3.5,2.5) E18(4,2.5) E19(4.5,2.5) F1(-4.5,2) F2(-4,2) F3(-3.5,2) F4(-3,2) F6(-2,2) F7(-1.5,2) F8(-1,2) F9(-0.5,2) F10(0,2) F11(0.5,2) F12(1,2) F13(1.5,2) F14(2,2) F16(3,2) F17(3.5,2) F18(4,2) F19(4.5,2) G1(-4.5,1.5) G2(-4,1.5) G3(-3.5,1.5) G4(-3,1.5) G6(-2,1.5) G7(-1.5,1.5) G8(-1,1.5) G9(-0.5,1.5) G10(0,1.5) G11(0.5,1.5) G12(1,1.5) G13(1.5,1.5) G14(2,1.5) G16(3,1.5) G17(3.5,1.5) G18(4,1.5) G19(4.5,1.5) H1(-4.5,1) H2(-4,1) H3(-3.5,1) H4(-3,1) H6(-2,1) H7(-1.5,1) H8(-1,1) H9(-0.5,1) H10(0,1) H11(0.5,1) H12(1,1) H13(1.5,1) H14(2,1) H16(3,1) H17(3.5,1) H18(4,1) H19(4.5,1) J1(-4.5,0.5) J2(-4,0.5) J3(-3.5,0.5) J4(-3,0.5) J6(-2,0.5) J7(-1.5,0.5) J8(-1,0.5) J9(-0.5,0.5) J10(0,0.5) J11(0.5,0.5) J12(1,0.5) J13(1.5,0.5) J14(2,0.5) J16(3,0.5) J17(3.5,0.5) J18(4,0.5) J19(4.5,0.5) K1(-4.5,0) K2(-4,0) K3(-3.5,0) K4(-3,0) K6(-2,0) K7(-1.5,0) K8(-1,0) K9(-0.5,0) K10(0,0) K11(0.5,0) K12(1,0) K13(1.5,0) K14(2,0) K16(3,0) K17(3.5,0) K18(4,0) K19(4.5,0) L1(-4.5,-0.5) L2(-4,-0.5) L3(-3.5,-0.5) L4(-3,-0.5) L6(-2,-0.5) L7(-1.5,-0.5) L8(-1,-0.5) L9(-0.5,-0.5) L10(0,-0.5) L11(0.5,-0.5) L12(1,-0.5) L13(1.5,-0.5) L14(2,-0.5) L16(3,-0.5) L17(3.5,-0.5) L18(4,-0.5) L19(4.5,-0.5) M1(-4.5,-1) M2(-4,-1) M3(-3.5,-1) M4(-3,-1) M6(-2,-1) M7(-1.5,-1) M8(-1,-1) M9(-0.5,-1) M10(0,-1) M11(0.5,-1) M12(1,-1) M13(1.5,-1) M14(2,-1) M16(3,-1) M17(3.5,-1) M18(4,-1) M19(4.5,-1) N1(-4.5,-1.5) N2(-4,-1.5) N3(-3.5,-1.5) N4(-3,-1.5) N6(-2,-1.5) N7(-1.5,-1.5) N8(-1,-1.5) N9(-0.5,-1.5) N10(0,-1.5) N11(0.5,-1.5) N12(1,-1.5) N13(1.5,-1.5) N14(2,-1.5) N16(3,-1.5) N17(3.5,-1.5) N18(4,-1.5) N19(4.5,-1.5) P1(-4.5,-2) P2(-4,-2) P3(-3.5,-2) P4(-3,-2) P6(-2,-2) P7(-1.5,-2) P8(-1,-2) P9(-0.5,-2) P10(0,-2) P11(0.5,-2) P12(1,-2) P13(1.5,-2) P14(2,-2) P16(3,-2) P17(3.5,-2) P18(4,-2) P19(4.5,-2) R1(-4.5,-2.5) R2(-4,-2.5) R3(-3.5,-2.5) R4(-3,-2.5) R6(-2,-2.5) R7(-1.5,-2.5) R8(-1,-2.5) R9(-0.5,-2.5) R10(0,-2.5) R11(0.5,-2.5) R12(1,-2.5) R13(1.5,-2.5) R14(2,-2.5) R16(3,-2.5) R17(3.5,-2.5) R18(4,-2.5) R19(4.5,-2.5) T1(-4.5,-3) T2(-4,-3) T3(-3.5,-3) T4(-3,-3) T5(-2.5,-3) T6(-2,-3) T7(-1.5,-3) T8(-1,-3) T9(-0.5,-3) T10(0,-3) T11(0.5,-3) T12(1,-3) T13(1.5,-3) T14(2,-3) T15(2.5,-3) T16(3,-3) T17(3.5,-3) T18(4,-3) T19(4.5,-3) U1(-4.5,-3.5) U2(-4,-3.5) U3(-3.5,-3.5) U4(-3,-3.5) U5(-2.5,-3.5) U6(-2,-3.5) U7(-1.5,-3.5) U8(-1,-3.5) U9(-0.5,-3.5) U10(0,-3.5) U11(0.5,-3.5) U12(1,-3.5) U13(1.5,-3.5) U14(2,-3.5) U15(2.5,-3.5) U16(3,-3.5) U17(3.5,-3.5) U18(4,-3.5) U19(4.5,-3.5) V1(-4.5,-4) V2(-4,-4) V3(-3.5,-4) V4(-3,-4) V5(-2.5,-4) V6(-2,-4) V7(-1.5,-4) V8(-1,-4) V9(-0.5,-4) V10(0,-4) V11(0.5,-4) V12(1,-4) V13(1.5,-4) V14(2,-4) V15(2.5,-4) V16(3,-4) V17(3.5,-4) V18(4,-4) V19(4.5,-4) W1(-4.5,-4.5) W2(-4,-4.5) W3(-3.5,-4.5) W4(-3,-4.5) W5(-2.5,-4.5) W6(-2,-4.5) W7(-1.5,-4.5) W8(-1,-4.5) W9(-0.5,-4.5) W10(0,-4.5) W11(0.5,-4.5) W12(1,-4.5) W13(1.5,-4.5) W14(2,-4.5) W15(2.5,-4.5) W16(3,-4.5) W17(3.5,-4.5) W18(4,-4.5) W19(4.5,-4.5)
  silkscreen extent -5.58,-5 5,5, body extent -5,-5 5,5, height 1.5
C_0402 [mm] "Capacitor 0402"
  rrect50% 0.6x0.65 smd mask+0: 1(-0.5,0) 2(0.5,0)
  silkscreen extent 0,-0.2 0,0.2, body extent -0.5,-0.3 0.5,0.3, height 0.2
C_01005#1 [mm] "01005 Capacitor"
  rect 0.26x0.22 smd mask+0: 1(-0.23,0) 2(0.23,0)
  silkscreen extent -0.5,-0.25 0.5,0.25, body extent -0.21,-0.11 0.21,0.11, height 0.22
C_01005#2 [mm] "01005 Capacitor"
  rect 0.26x0.22 smd paste+0 mask+0: 1(-0.23,0) 2(0.23,0)
  silkscreen extent -0.5,-0.25 0.5,0.25, body extent -0.21,-0.11 0.21,0.11, height 0.22
C_ERA-0402 [mm]
  rect 0.5x0.6 smd mask+0: 1(-0.5,0) 2(0.5,0)
  silkscreen extent 0,-0.3 0,0.3, body extent -0.5,-0.3 0.5,0.3, height 0.2
C_ERA-0603 [mm]
  rect 1.1x1 smd mask+0: 1(-0.85,0) 2(0.85,0)
  silkscreen extent -0.64,-0.64 0.64,0.64, body extent -0.8,-0.4 0.8,0.4, height 0.3
C_ERA-0805 [mm]
  rect 1.3x1.5 smd mask+0: 1(-0.95,0) 2(0.95,0)
  silkscreen extent -0.64,-0.89 0.64,0.89, body extent -0.94,-0.63 1.06,0.63, height 0.78
CAPC0201 [mm] "Chip Capacitor, Body 0.6x0.3mm, Height 0.33mm, IPC Medium Density"
  rect 0.46x0.42 smd mask+0: 1(-0.33,0) 2(0.33,0)
  silkscreen extent -0.66,-0.3 0.67,0.3, body extent -0.31,-0.16 0.32,0.17, height 0.33
DFN6 [mm] "QFN, 6-Leads, Body 2.1x2.1mm (max), Pitch 0.50mm, IPC High Density"
  rect 0.25x0.675 smd mask+0: 1(-0.5,-0.91) 2(0,-0.91) 3(0.5,-0.91) 4(0.5,0.91) 5(0,0.91) 6(-0.5,0.91)
  rect 1.42x0.61 smd mask+0: 7(0,0)
  silkscreen extent -1.14,-1.05 1.05,1.05, body extent -1.05,-1.05 1.05,1.05, height 0.8
DSBGA4 [mm] "BGA, 4-Leads"
  round 0.18 smd mask+0.025: A1(-0.175,-0.175) A2(-0.175,0.175) B1(0.175,-0.175) B2(0.175,0.175)
  silkscreen extent -0.55,-0.55 0.5,0.5, body extent -0.33,-0.35 0.35,0.35, height 0.6
DSBGA4_.4MM [mm] "BGA, 4-Leads"
  round 0.25 smd mask+0.025: A1(-0.2,0.2) A2(0.2,0.2) B1(-0.2,-0.2) B2(0.2,-0.2)
  silkscreen extent -0.55,-0.5 0.5,0.55, body extent -0.4,-0.4 0.4,0.4, height 0.5
EPM_3X_CON_BO [mm] "EPM PAD"
  rrect50% 0.75x0.5 smd mask+0: 0(-0.363,-2.66) 2(-0.363,-4.717)
  rrect50% 0.5x1 smd mask+0: 0(-0.31,0.535)
  rrect50% 0.5x0.686 smd mask+0: 0(-0.261,-5.448)
  rrect50% 0.508x0.762 smd mask+0: 1(-0.363,-1.847) 3(-0.279,-7.517)
  body extent 0.66,-8.18 7.57,0.94, height 2.55
EPM_3X_CON_FRANK [mm] "EPM PAD"
  rrect50% 0.75x0.5 smd mask+0: 0(-0.397,2.532) 0(-0.346,5.402) 1(-0.363,1.847) 2(-0.347,4.744) 3(-0.346,7.561)
  rrect50% 0.5x1 smd mask+0: 0(-0.31,-0.535)
  body extent 1.7,-0.94 8.61,8.18, height 2.55
FID_FAIRCHILD [mil]
KX2513G0032.768000 [mm]
  rect 1.2x1 smd mask+0: 1(-0.85,-0.65) 2(0.85,-0.65) 3(0.85,0.65) 4(-0.85,0.65)
  silkscreen extent -1.95,-1.33 1.65,0.87, body extent -1.25,-1 1.25,1, height 1
L_0806 [mm] "Inductor 0806"
  rrect50% 1.3x1.8 smd mask+0: 1(1,0) 2(-1,0)
  silkscreen extent -0.15,-0.81 0.15,0.79, body extent -1,-0.63 1,0.62, height 0.78
L_SMD_2.2UH [mm] "Inductor"
  rect 1.4x1.7 smd mask+0: 1(1,0) 2(-1,0)
  Component Side region: 0.3,0.85 0.3,1.7 0.85,1.7 1.7,0.85
  Component Side region: -0.3,0.85 -0.3,1.7 -0.85,1.7 -1.7,0.85
  Component Side region: -0.3,-0.85 -0.3,-1.7 -0.85,-1.7 -1.7,-0.85
  Component Side region: 0.3,-0.85 0.3,-1.7 0.85,-1.7 1.7,-0.85
  silkscreen extent -0.15,-1.9 0.15,1.91, body extent -1.7,-1.7 1.7,1.7, height 1.2
LCCS165P160X200X70-4N [mm]
  rect 0.7x0.6 smd mask+0: 1(-0.7,-0.55) 2(0.7,-0.55) 3(0.7,0.55) 4(-0.7,0.55)
  silkscreen extent -1.4,-1.45 1.38,0.87, body extent -1.05,-0.85 1.05,0.85, height 1.2
"MICRP SIP"#1 [mm]
  round 0.3 smd paste+0.02 mask+0.03: A1(-1,0.8) A2(0,0.8) A3(1,0.8) B1(-1,0) B2(0,0) C1(-1,-0.8) C2(0,-0.8) C3(1,-0.8)
  silkscreen extent -1.8,-1.17 1.48,1.17, body extent -1.48,-1.17 1.48,1.17, height 1
"MICRP SIP"#2 [mm]
  round 0.3 smd paste+0 mask+0: A1(-1,0.8) A2(0,0.8) A3(1,0.8) B1(-1,0) B2(0,0) C1(-1,-0.8) C2(0,-0.8) C3(1,-0.8)
  silkscreen extent -1.8,-1.17 1.48,1.17, body extent -1.48,-1.17 1.48,1.17, height 1
QFN40P300X300X80_HS-13L [mm] "QFN, 12-Leads, Body 3.00x3.00mm, Pitch 0.40mm, Thermal Pad 2.50x1.60mm, IPC High Density"
  rect 0.25x0.5 smd mask+0: 1(-1,-1.275) 2(-0.6,-1.275) 3(-0.2,-1.275) 4(0.2,-1.275) 5(0.6,-1.275) 6(1,-1.275) 7(1,1.275) 8(0.6,1.275) 9(0.2,1.275) 10(-0.2,1.275) 11(-0.6,1.275) 12(-1,1.275)
  rect 2.5x1.6 smd mask+0: 13(0,0)
  silkscreen extent -1.7,-2.03 1.7,1.7, body extent -1.5,-1.5 1.5,1.5, height 0.8
R_0402 [mm] "Resistor 0402"
  rrect50% 0.6x0.65 smd mask+0: 1(-0.5,0) 2(0.5,0)
  silkscreen extent 0,-0.2 0,0.2, body extent -0.51,-0.25 0.51,0.25, height 0.51
R_01005#1 [mm] "Chip Capacitor, Body 0.4x0.2mm, Height 0.22mm, IPC High Density"
  rect 0.26x0.22 smd mask+0: 1(-0.23,0) 2(0.23,0)
  silkscreen extent -0.5,-0.25 0.5,0.25, body extent -0.21,-0.11 0.21,0.11, height 0.22
R_01005#2 [mm] "Chip Capacitor, Body 0.4x0.2mm, Height 0.22mm, IPC High Density"
  rect 0.26x0.22 smd paste+0 mask+0: 1(-0.23,0) 2(0.23,0)
  silkscreen extent -0.5,-0.25 0.5,0.25, body extent -0.21,-0.11 0.21,0.11, height 0.22
RFSHIELD_1X2_MODULE [mm]
  rect 0.254x1.5 smd mask+0: S(0.15,23) S(0.15,25.5)
  rect 0.254x2 smd mask+0: S(0.15,36.3) S(0.15,39)
  rect 2x0.254 smd mask+0: S(1.5,40.35) S(4.3,40.35)
  rect 0.254x3 smd mask+0: S(1.55,2) S(1.55,6.5) S(1.55,10.5) S(1.55,14.5) S(1.55,18.5) S(17.85,2.5) S(17.85,6.5) S(17.85,10.5) S(17.85,14.5) S(17.85,18.5) S(17.85,22.5) S(17.85,26.5) S(17.85,30.5) S(17.85,34.5) S(17.85,38.5)
  rect 3x0.254 smd mask+0: S(3.5,0.15) S(7.633,0.15) S(11.767,0.15) S(15.9,0.15)
  rect 3x0.203 smd mask+0: S(15.6,40.35)
SP-9XUH-D [mm]
  rect 0.3x1 smd mask+0: 1(-3.85,-3.7) 2(-3.3,-3.7) 3(-2.75,-3.7) 4(-2.2,-3.7) 5(-1.65,-3.7) 6(-1.1,-3.7) 7(-0.55,-3.7) 8(0,-3.7) 9(0.55,-3.7) 10(1.1,-3.7) 11(1.65,-3.7) 12(2.2,-3.7) 13(2.75,-3.7) 14(3.3,-3.7) 15(3.85,-3.7) 27(3.85,3.7) 28(3.3,3.7) 29(2.75,3.7) 30(2.2,3.7) 31(1.65,3.7) 32(1.1,3.7) 33(0.55,3.7) 34(0,3.7) 35(-0.55,3.7) 36(-1.1,3.7) 37(-1.65,3.7) 38(-2.2,3.7) 39(-2.75,3.7) 40(-3.3,3.7) 41(-3.85,3.7)
  rect 1x0.3 smd mask+0: 16(4.1,-2.75) 17(4.1,-2.2) 18(4.1,-1.65) 19(4.1,-1.1) 20(4.1,-0.55) 21(4.1,0) 22(4.1,0.55) 23(4.1,1.1) 24(4.1,1.65) 25(4.1,2.2) 26(4.1,2.75) 42(-4.1,2.75) 43(-4.1,2.2) 44(-4.1,1.65) 45(-4.1,1.1) 46(-4.1,0.55) 47(-4.1,0) 48(-4.1,-0.55) 49(-4.1,-1.1) 50(-4.1,-1.65) 51(-4.1,-2.2) 52(-4.1,-2.75)
  rect 0.8x0.8 smd mask+0: 53(-1.2,-2.1) 54(0,-2.1) 55(1.2,-2.1) 56(1.2,-0.7) 57(1.2,0.7) 58(1.2,2.1) 59(0,2.1) 60(-1.2,2.1) 61(-1.2,0.7) 62(-1.2,-0.7) 63(0,-0.7) 64(0,0.7)
  rect 0.4x0.4 smd mask+0: 65(3.05,-1.65) 66(2.7,-1) 67(3.05,-0.35) 68(2.7,0.3) 69(3.05,1.1)
  silkscreen extent -5,-4.25 4.6,4.25, body extent -4.62,-4.25 4.6,4.25, height 1.35
TSSLP-2-1 [mm]
  rect 0.24x0.32 smd mask+0: 1(-0.178,0) 2(0.178,0)
  silkscreen extent -0.5,-0.2 -0.5,0.2
UFDFN8 [mm]
  rect 1x0.3 smd mask+0: 1(-1.2,1.2) 2(-1.2,0.4) 3(-1.2,-0.4) 4(-1.2,-1.2) 5(1.2,-1.2) 6(1.2,-0.4) 7(1.2,0.4) 8(1.2,1.2)
  rect 0.3x2.4 smd mask+0: 9(0,0)
  silkscreen extent -2.2,-2.2 1.5,2.2, body extent -1.5,-2 1.5,2, height 0.6
W.FL2-R-SMT-1 [mm]
  rect 0.5x0.65 smd mask+0: 1(0,-0.975)
  rect 0.5x0.55 smd mask+0: 2(0,1.025)
  rect 0.6x1.5 smd mask+0: 3(-1,0) 4(1,0)
  Mechanical 13 keep-out region: -0.373,-0.5 0.377,-0.5 0.377,0.5 -0.373,0.5
  body extent -1.38,-1.4 1.35,1.4, height 0.8

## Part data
ANT1: library part ANT_W.FL2-R-SMT-1(40), "CONN W.FL JACK STR 50 OHM SMD"
C1 C3 C4 C5 C6 C7 C12 C13 C14 C15 C17 C18 C19 C20 C21 C22 C23 C24 C25 C26 C27 C28 C29 C30 C33 C34 C35 C36 C41 C42 C43 C44 C45 C46 C47 C48 C49 C51 C53 C54 C55 C56 C58 C62 C63 C64 C65 C66 C67 C68 C69 C70 C71 C73 C74 C75 C94: library part C_01005_0.1uF, "CAP CER 0.1UF 6.3V 20% X5R 01005"
C2: library part C_0201_0.1UF, "CAP CER 0.1UF 6.3V 10% X5R 0201"
C8: "CAP CER 22PF 50V 5% NP0 0201"
C9 C10 C11 C39 C40: library part C_0805_22礔_35V, "CAP CER 22UF 35V 20% JB 0805"
C16 C31 C37: library part C_0402_1.0UF_16V, "CAP CER 1.0UF 16V X5R 0402"
C32 C38 C78: library part C_0805_22UF_6.3V, "CAP CER 22UF 6.3V X7R 10% 0805"
C50 C59 C60 C61 C72 C82: library part C_0402_10uF, "CAP CER 10UF 4V 20% X5R 0402"
C52 C95: library part C_0603_22uF, "CAP CER 22UF 6.3V 20% X5R 0603"
C57 C77: library part C_0201_0.47礔, "CAP CER 0.47UF 6.3V 20% JB 0201"
C81: library part C_0402_4.7uF, "CAP CER 4.7UF 6.3V 10% X7R 0603"
D1 D2 D3 D4: library part D_SBR0240LP-7, "DIODE SUP BARRIER 40V 0.25A 2DFN"
J1: library part J_EPM_3_PAD_BO
J2: library part J_EPM_3_PAD_FRANK
J3: library part J_TONKA_MODULE_CONNECTOR
L1: library part L_0806_22uH, "INDUCTOR 22UH 10% 0806 SMD"
L5: library part L_0805_2.2uH_160mOhm, "INDUCTOR MULTILAYER 2.2UH 0805"
L6: library part L_SMD_2.2uH, "COIL CHOKE 2.2UH SHIELDED SMD"
Q1 Q4 Q5 Q6 Q15 Q16 Q17: library part Q_PFET_BGA_30V, "MOSFET P-CH D-S 30V MICROFOOT"
Q2 Q3 Q7 Q8 Q9 Q10 Q11 Q12 Q18 Q19 Q20 Q21 Q22 Q23: library part Q_NFET_BGA_30V, "MOSFET N-CH D-S 30V MICROFOOT"
R1 R2 R3 R4 R5 R6 R52: library part R_01005_33, "RES 33 OHM 1/32W 1% 01005"
R9 R17 R18 R19 R53 R54 R55: library part R_0402_100_5%_PW, "RES 100 OHM 1/5W 5% 0402 SMD"
R10 R15 R22 R23 R24 R25 R26 R30 R33 R34 R36 R39 R64 R65 R66 R69: library part R_01005_10K, "RES 10K OHM 1/32W 1% 01005"
R11 R35 R38 R40 R56 R57 R58: library part R_0402_270_5%_PW, "RES 270 OHM 1/5W 5% 0402 SMD"
R12 R16 R20 R21 R41 R42 R44 R59 R60 R61 R63: library part R_01005_1k, "RES 1K OHM 1/32W 1% 01005 SM"
R13 R47: library part R_01005_100K, "RES 100K OHM 1/32W 1% 01005 SMD"
R14 R27 R28 R29 R32: library part R_01005_4.7k, "RES 4.7K OHM 1/32W 1% 01005 SMD"
R37 R62 R67 R68: library part R_01005_1M, "RES 1M OHM 1/32W 1% 01005 SMD"
S1: library part S_RF_SHIELD_1X2_MODULE
T1: library part TEST_INTERFACE, "8 PIN Test Interface"
TVS1 TVS2 TVS3 TVS4 TVS5 TVS6 TVS7 TVS8 TVS9: "TVS DIODE 5.3VWM 28VC TSSLP2-1"
U1: "IC REG BUCK SYNC 1.8V 0.6A 8USIP"
U2: library part U_MURATA_WIFI, "Embedded Solutions>Wireless Modules>Wireless LAN (WIFI)"
U3: library part U_LFE3-17EA-MG328, "IC FPGA 17KLUTS 116I/O 328-BGA"
U4: library part U_LTC3460-1, "IC REG BOOST ADJ 0.18A 6DFN"
U5: library part U_M25P16-VMC6TG, "IC FLASH 16MBIT 75MHZ 8UFDFPN"
U6 U8: library part U_SN74AUP1G34YFPR, "IC BUFFER GATE SGL 4-DSBGA"
U7: library part U_LM3668SD-2833/NOPB, "IC REG BUCK BST SYNC ADJ 12-LLP"
U9: library part U_ASA-19.200MHZ-L-T, "OSC 19.200 MHZ 3.3V SMD"
U10: library part U_KX2513G0032.768000, "OSC XO 32.768KHZ SMD"
U11: library part U_TPS82675SIPT, "IC REG BUCK SYNC 1.2V 0.6A 8USIP"
U12: library part U_LM3671TL-2.5/NOPB, "IC REG BUCK SYNC 2.5V 0.6A 5USMD"
U13: library part U_FPF1504BUCX, "IC LOAD MGMT SWITCH ADV 4WLCSP"

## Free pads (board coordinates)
  round 39.37 smd mask+5: FIDUCIAL(54,1553) FIDUCIAL(105,358) FIDUCIAL(672,128)
  round 39.37 smd far side mask+10: FIDUCIAL(56,1562) FIDUCIAL(198,432) FIDUCIAL(645,192)

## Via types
v1: diameter 12, hole 6, Component Side to Solder Side, tented both sides, 479 vias

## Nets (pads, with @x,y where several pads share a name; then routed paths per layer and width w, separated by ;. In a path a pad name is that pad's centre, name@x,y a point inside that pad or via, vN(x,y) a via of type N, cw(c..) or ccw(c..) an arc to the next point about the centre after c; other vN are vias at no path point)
32KHZ_CLK: U2.23 U10.3 | length 128.2
  Component Side w8: U10.3@94.41,139.46 94.41,159.41 110,175 168,175 174.31,168.69 U2.23@193.58,168.69
BAT+: C50.2 C81.2 J3.1 R39.1 TVS7.1 U7.5 U7.7 U7.11 U12.A1 | length 1241.2
  Component Side w8: U7.5@636.81,947.84 636.81,933.19 648.1,921.9 655.7,921.9 ; U7.7@653.33,1049 U7.7@652.56,1048.23 652.56,1056.56 v1(665,1069)
  Component Side w10: C50.2@517,974.69 531.69,974.69 544,987 v1(544,1013) ; v1(571,1072) 582,1072 589,1065 589,1048.8 U7.11@589.57,1048.23 ; v1(609.84,615.78) 619.06,625 C81.2@629.31,625 629.31,591.2 U12.A1@627.16,589.05
  Inner Layer 1 w20: J3.1@325.08,994.4 329.47,990 393,990 429,1026 480,1026 493,1013 v1(544,1013) 571,1040 v1(571,1072)
  Inner Layer 2 w10: v1(609.84,615.78) 619.78,615.78 655,651 655,677 684,706 684,713.23 684,720 684,763 661.1,785.9 v1(661.1,916.5)
  Solder Side w8: J3.1@325.08,994.4 333.47,986 TVS7.1@385.7,986
  Solder Side w10: v1(571,1072) 584,1085 649,1085 v1(665,1069) 655,1059 R39.1@655,969.06 ; R39.1@655.06,969 R39.1@655,969.06 ; v1(661.1,916.5) 672.5,916.5 681,925 681,959 670.94,969.06 R39.1@655,969.06
BT_RESETX: U2.5 U3.B6 | length 221.4
  Component Side w5: U2.5@419.96,357.67 419.96,374.96 v1@434.5,389.5
  Inner Layer 2 w5: v1(385.83,552.17) 385.83,515.17 399,502 399,469 426.5,441.5 426.5,426.79 435,418.29 v1(435,389)
BT_WAKEUP: U2.33 U3.C6 | length 743.1
  Component Side w5: v1(227,320) 267,280 267,110 275,102 325,102 333.35,93.65 U2.33@333.35,66.33
  Inner Layer 2 w5: v1(227,320) 227,349 200,376 200,411 243,454 243,474 273,504 273,549 321,597 365,597 385.83,576.17 v1(385.83,571.85)
C_RX_CLK_N: C54.1 J3.6 R65.1 R67.1 TVS9.1 | length 1004.9
  Component Side w4: J3.6@234.53,1175.5 279.03,1131 357,1131 380,1154 v1(380,1172)
  Inner Layer 2 w4: v1(372,1056) 377,1051 393.97,1051 406.97,1038 420.03,1038 431,1048.97 431,1151 406,1176 385.47,1176 381.47,1172 v1(380,1172)
  Solder Side w4: v1(372,1056) 376,1052 394,1052 402,1044 412.91,1044 426.15,1030.76 426.15,1020.55 427.7,1019 TVS9.1@434.69,1012 428.63,1005.93 428.63,996.34 457.97,967 506,967 549.59,923.41 549.59,908.38 573,884.97 573,773 544,744 544,727.03 529.97,713 514.65,713 C54.1@509.65,708 ; v1(380,1172) 383,1172 389,1178 407.06,1178 408,1177.06 R67.1@415,1177.06 R65.1@438,1177.06
C_RX_CLK_P: C53.1 J3.8 R66.1 R68.1 TVS8.1 | length 1004.4
  Component Side w4: J3.8@234.53,1266.05 280.58,1220 353,1220 v1(379.92,1193.08)
  Inner Layer 2 w4: v1(372,1032) 379,1039 389,1039 402,1026 425,1026 443,1044 443,1155.97 410.97,1188 385,1188 v1(379.92,1193.08)
  Solder Side w4: v1(372,1032) 372,1036 376,1040 389.03,1040 397.03,1032 407.94,1032 414.15,1025.79 414.15,1020.55 TVS8.1@405.61,1012 409,1012 418,1003 418,990 453,955 501.03,955 537.59,918.44 537.59,903.41 561,880 561,777.97 532,748.97 532,732 525,725 514.79,725 C53.1@509.79,730 ; v1(379.92,1193.08) 383.51,1189.49 401,1189.49 405,1193.49 405,1198 407.94,1200.94 R68.1@415,1200.94 R66.1@438,1200.94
